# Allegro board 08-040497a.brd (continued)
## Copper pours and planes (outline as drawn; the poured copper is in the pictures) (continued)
UNNAMED_4_ADP2301_I57_BST on TOP: 176,89.75 174.5,89.75 174.5,87 176,87
UNNAMED_4_ADP2301_I57_EN on TOP: 162.75,89 161,89 161,84 162.75,84
UNNAMED_4_ADP2301_I57_FB on TOP: 174.75,92.75 174.75,91.25 176.25,91.25 177,90.5 178.75,90.5 179.25,91 181,91 181,92.75
UNNAMED_4_ADP2301_I57_SW on TOP: 172,90 172,85 171.5,84.5 169.25,84.5 169.25,81.75 174.5,81.75 174.5,85.75 173.75,86.5 173.75,88.5 173.25,89 173.25,90
UNNAMED_4_ADP3303_I47_NR on TOP: 135.25,74.75 139.25,74.75 139.25,74 135.25,74
UNNAMED_4_ADP3303_I47_OUT on TOP: 135.25,73.5 139.75,73.5 140,73.75 141.25,73.75 141.25,72.25 140,71 135.25,71
UNNAMED_4_CAP_I91_N2 on TOP: 155.25,89.25 152.75,89.25 152.5,89 152.5,85.5 152.75,85.25 155,85.25 155.25,85.5
UNNAMED_4_CN2P_I42_N1 on TOP: 124.5,97 119.75,97 118,95.25 118,69.75 118.25,69.5 121.75,69.5 125,72.75 125,96.5
UNNAMED_4_CN4PV2_I45_N3 on TOP: 98,97 102.5,97 103.5,96 103.5,75.75 106.25,73 113.75,73 114.25,72.5 114.25,69.75 114,69.5 101.25,69.5 97.75,73 97.75,96.75
V_IN on TOP: 115,72.75 117,72.75 117.25,72.5 117.25,69.25 117.75,68.75 122.25,68.75 126.25,72.75 126.25,87 134.25,95 167.25,95 171.5,90.75 173.25,90.75 173.25,90.5 173,90.25 171.5,90.25 170.75,89.5 169.25,89.5 168.75,89 166,89 163,92 137.25,92 133.5,88.25 133.5,86 134.5,85 142.25,85 142.25,84 141.5,84 141,83.5 141,80.75 139.75,79.5 132.25,79.5 131.75,79 131.75,75.5 129.25,75.5 129.25,73.5 129.5,73.25 132.25,73.25 132.25,71.5 131.75,71 131.5,71 131.25,70.75 131.25,66.5 130,65.25 115.75,65.25 115,66
VDET on TOP: 59.75,59.5 56.5,59.5 53.25,56.25 53.25,51.75 53.5,51.5 53.5,50.75 54.5,50.75 59.75,56
VDET on TOP: 148,69.5 152.75,69.5 152.75,64.25 148,64.25
VDET on TOP: 155.25,81 152.5,81 152.5,77 152.75,76.75 155,76.75 155.25,77
VDET on BOTTOM: 152.25,80.25 152.25,71.25 148,67 148,64.5 148.25,64.25 152.75,64.25 156.25,67.75 156.25,80.25
VDET on BOTTOM: 148.25,67 80.25,67 72.75,59.5 56,59.5 56,56.5 57,55.5 75.5,55.5 84.25,64.25 148.75,64.25 148.75,66.5
VDRIVE on TOP: 164.75,47.25 142.5,47.25 129,60.75 115.75,60.75 107.5,52.5 101.75,52.5 101.75,51 110,51 117,58 127,58 141,44 164.5,44 164.75,44.25
VIO_CONNECTOR on TOP: 167,47.25 168,48.25 184.75,48.25 189,44 191.5,44 191.5,43.5 189,43.5 188.5,43 169.25,43 167,45.25
VNEG on TOP: 99.75,28 120.25,28 121,27.25 121,12.75 119.25,11 99.75,11 99.75,13.5 116.75,13.5 117.75,14.5 117.75,24.75 116.75,25.75 105.5,25.75 103.75,24 100.5,24 100.5,24.5 99.75,25.25
VNEG on TOP: 147,53.5 147,48.25 153.25,48.25 153.5,48.5 153.5,53.5
VNEG on BOTTOM: 151.75,51.75 142.5,51.75 116.38,25.62 119.5,22.5 120.75,22.5 146.5,48.25 151.75,48.25
VSDP on TOP: 177,90 177,62.25 193.25,46 197.5,46 197.5,47.25 194.5,47.25 184.25,57.5 184.25,84 184,84.25 180.75,84.25 178.75,86.25 178.75,90
VSDP_EN on TOP: 163.25,83.5 161,83.5 160.75,83.25 160.75,77.5 158.25,75 142.75,75 142,74.25 142,72.5 142.25,72.25 147.75,72.25 148.75,71.25 159.5,71.25 163.5,75.25 163.5,83.25

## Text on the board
Ref Des/Silkscreen Top: EV-VSWR-SDZ | 08-040497 Rev-A
DIMENSION: Note the 8x half-moon holes at board edge. | These are plated and connected to the GND plane on all 4 layers. | SEE NOTE 13 | 16   NOTE THE SIX HOLES AT THE EDGE OF THE BOARD THAT WILL BE A HALF MOON AND PLATED. | 15.    FINISHED BOARD MUST BE ROHS & REACH COMLPIANT. | FR4 CORE
User.17: L02-GROUND PLANE | 08-      -08
User.18: L03 - GROUND PLANE | 08-      -09
User.45: FIGURE | SIZE | 0.254 | 0.4064 | 0.9906 | 1.016 | 1.143 | 1.397 | 1.6002 | 1.905 | 2.1082 | 0.7112 | 1.0922 | 1.8034 | 3.175 | DRILL CHART: TOP to BOTTOM | ALL UNITS ARE IN MILLIMETERS | PLATED | NON-PLATED | QTY | 1615 | 55 | 8 | 2 | 3 | 4 | 16 | 1
